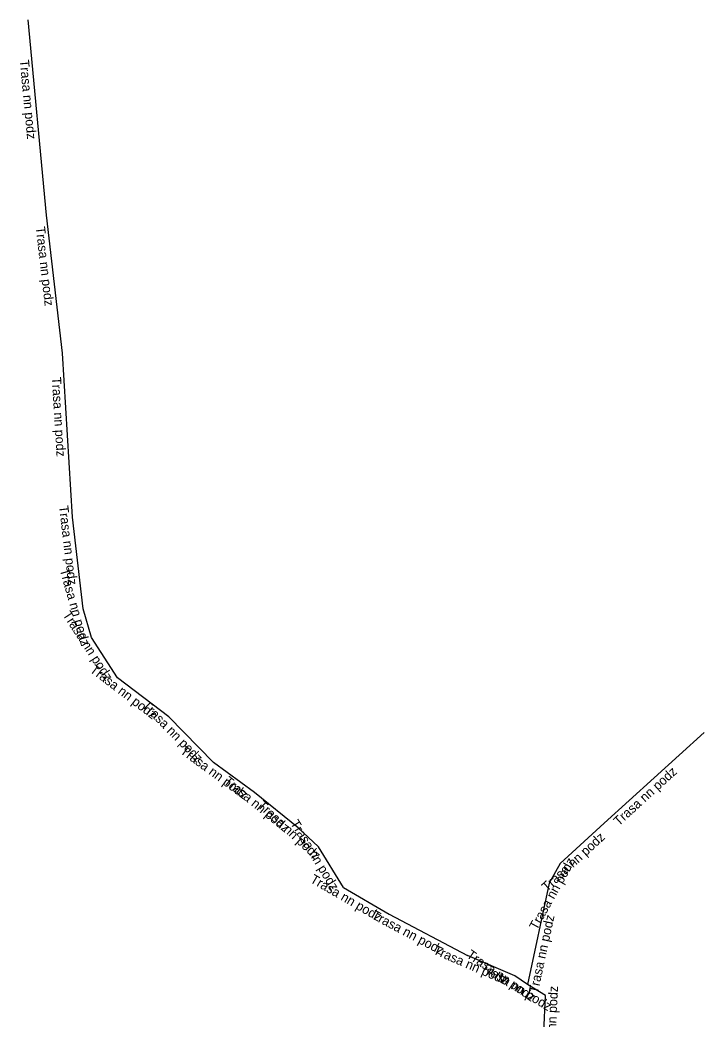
# Model space of a CAD drawing. Extents: x -651117 to -650186, y -983707 to -983198.
# Drawn here: x -650253 to -650216.4, y -983441.3 to -983387.8 of the extents above; entities that cross this region are included whole.
import ezdxf

# ---------------------------------------------------------------- set-up
doc = ezdxf.new("R2010")
doc.units = 0
doc.layers.add('Popiskový text - Ostatní atributy Trasy', color=7, linetype='Continuous')
doc.layers.add('Spojnice NN', color=7, linetype='Continuous')

msp = doc.modelspace()

# ---------------------------------------------------------------- linework, layer by layer
at = {"layer": 'Spojnice NN'}
for points in [[(-650251.62, -983398.28), (-650252.61, -983387.84)], [(-650250.77, -983405.68), (-650251.62, -983398.28)], [(-650250.23, -983414.45), (-650250.77, -983405.68)], [(-650249.65, -983419.36), (-650250.23, -983414.45)], [(-650249.22, -983420.88), (-650249.65, -983419.36)], [(-650247.82, -983423.04), (-650249.22, -983420.88)], [(-650245.07, -983425.14), (-650247.82, -983423.04)], [(-650242.68, -983427.58), (-650245.07, -983425.14)], [(-650216.41, -983425.97), (-650221.76, -983430.83)], [(-650240.48, -983429.19), (-650242.68, -983427.58)], [(-650238.15, -983431.08), (-650240.48, -983429.19)], [(-650237.05, -983432.09), (-650238.15, -983431.08)], [(-650221.76, -983430.83), (-650224.12, -983432.99)], [(-650235.72, -983434.27), (-650237.05, -983432.09)], [(-650224.12, -983432.99), (-650224.7, -983434.04)], [(-650235.72, -983434.27), (-650233.27, -983435.69)], [(-650224.7, -983434.04), (-650225.872, -983439.458)], [(-650233.27, -983435.69), (-650229.08, -983437.9)], [(-650226.55, -983438.99), (-650229.08, -983437.9)], [(-650225.872, -983439.458), (-650226.55, -983438.99)], [(-650224.9, -983440.05), (-650225.872, -983439.458)], [(-650224.953, -983441.227), (-650224.9, -983440.05)], [(-650225.06, -983443.69), (-650224.953, -983441.227)]]:
    msp.add_lwpolyline(points, dxfattribs=at)

# ---------------------------------------------------------------- texts
at = {"layer": 'Popiskový text - Ostatní atributy Trasy'}
for rotation, p in [(275.417, (-650253.059, -983389.988)), (276.5526, (-650252.2, -983398.927)), (273.5235, (-650251.342, -983406.964)), (276.7369, (-650250.955, -983413.855)), (285.7959, (-650250.917, -983417.268)), (302.9492, (-650250.778, -983419.673)), (322.6333, (-650249.341, -983422.696)), (314.4069, (-650246.542, -983424.566)), (323.8027, (-650244.504, -983427.051)), (42.2524, (-650220.978, -983430.998)), (320.9525, (-650242.169, -983428.657)), (317.4424, (-650240.359, -983429.935)), (301.387, (-650238.579, -983430.831)), (42.4664, (-650224.823, -983434.515)), (61.0846, (-650225.363, -983436.584)), (329.9038, (-650237.545, -983433.964)), (332.1908, (-650234.263, -983435.902)), (77.7941, (-650225.316, -983439.963)), (336.6922, (-650230.963, -983437.796)), (325.384, (-650229.17, -983437.971)), (328.6563, (-650228.412, -983438.672)), (87.4217, (-650224.419, -983443.812))]:
    msp.add_text('Trasa nn podz', height=0.5, rotation=rotation, dxfattribs=at).set_placement(p)

doc.saveas('drawing.dxf')
